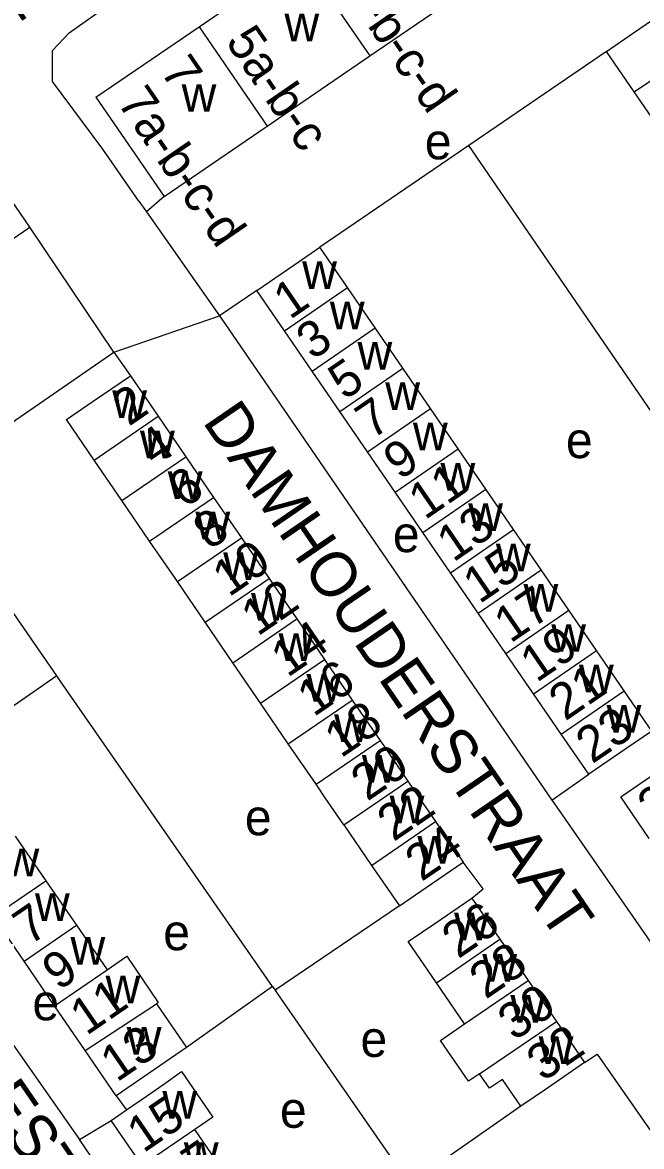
# Model space of a CAD drawing. Extents: x 157569 to 159501, y 382907 to 384670.
# Drawn here: x 158188.6 to 158257.4, y 383461.2 to 383586.2 of the extents above; entities that cross this region are included whole.
import ezdxf

# ---------------------------------------------------------------- set-up
doc = ezdxf.new("R2010")
doc.units = 0
for name, color, linetype in [('BLT_Basislijn', 7, 'Continuous'), ('BLT_Bebouwing', 7, 'Continuous'), ('BLT_Centroide', 7, 'Continuous'), ('BLT_Huisnummer', 7, 'Continuous'), ('BLT_Huisnummer_ tussenligend', 7, 'Continuous'), ('BLT_Huisnummer_reeks', 7, 'Continuous'), ('BLT_Onderverdeling_panden', 7, 'Continuous'), ('BLT_Straatnaam', 7, 'Continuous'), ('BLT_Vlakafsluiter', 7, 'Continuous')]:
    doc.layers.add(name, color=color, linetype=linetype)

msp = doc.modelspace()

# ---------------------------------------------------------------- linework, layer by layer
at = {"layer": 'BLT_Basislijn'}
for p, q in [((158253.53, 383582.97), (158238.22, 383572.51)), ((158238.22, 383572.51), (158221.67, 383561.19)), ((158263.17, 383536.11), (158238.22, 383572.51)), ((158201.56, 383566.31), (158202.39, 383565.13)), ((158204.37, 383566.82), (158202.39, 383565.13)), ((158202.39, 383565.13), (158210.52, 383553.57)), ((158198.77, 383549.53), (158189.43, 383563.44)), ((158214.66, 383556.38), (158210.52, 383553.57)), ((158177.61, 383534.96), (158198.77, 383549.53)), ((158198.77, 383549.53), (158200.61, 383546.91)), ((158192.45, 383513.55), (158177.61, 383534.96)), ((158192.45, 383513.55), (158186.37, 383509.34)), ((158247.46, 383499.74), (158251.56, 383502.6)), ((158230.51, 383487.97), (158216.7, 383478.6)), ((158216.41, 383479.02), (158206.85, 383472.24)), ((158216.41, 383479.02), (158216.7, 383478.6)), ((158199.04, 383466.86), (158200.16, 383465.29)), ((158244.02, 383465.72), (158231.59, 383457.07)), ((158194.95, 383462), (158198.47, 383464.12)), ((158208.98, 383441.63), (158194.95, 383462))]:
    msp.add_line(p, q, dxfattribs=at)
for points in [[(158201.56, 383566.31), (158197.56, 383572.1), (158191.94, 383579.6), (158191.94, 383583.05), (158193.8, 383585.03), (158215.11, 383600.13)], [(158210.52, 383553.57), (158210.7, 383553.32), (158247.46, 383499.74)], [(158216.41, 383479.02), (158192.82, 383513.01), (158192.45, 383513.55)], [(158247.46, 383499.74), (158247.67, 383499.43), (158262.36, 383478.24), (158263.44, 383478.98)], [(158169.81, 383497.81), (158170.18, 383497.34), (158194.51, 383462.64), (158194.95, 383462)], [(158238.55, 383488.85), (158239.83, 383489.88), (158237.6, 383492.84)], [(158216.7, 383478.6), (158216.97, 383478.21), (158231.59, 383457.07)], [(158251.08, 383470.55), (158252.5, 383471.5), (158264.68, 383454)]]:
    msp.add_lwpolyline(points, dxfattribs=at)
at = {"layer": 'BLT_Bebouwing'}
for p, q in [((158208.24, 383585.71), (158219.63, 383593.5)), ((158227.21, 383582.46), (158238.6, 383590.25)), ((158196.77, 383577.87), (158208.24, 383585.71)), ((158215.82, 383574.66), (158227.21, 383582.46)), ((158256.61, 383578.46), (158253.53, 383582.97)), ((158196.77, 383577.87), (158204.37, 383566.82)), ((158259.7, 383573.95), (158256.61, 383578.46)), ((158204.37, 383566.82), (158215.82, 383574.66)), ((158189.43, 383563.44), (158185.14, 383569.68)), ((158224.74, 383556.71), (158221.67, 383561.19)), ((158217.73, 383551.9), (158214.66, 383556.38)), ((158227.82, 383552.23), (158224.74, 383556.71)), ((158220.81, 383547.42), (158217.73, 383551.9)), ((158230.89, 383547.75), (158227.82, 383552.23)), ((158233.97, 383543.26), (158230.89, 383547.75)), ((158200.61, 383546.91), (158203.69, 383542.4)), ((158223.88, 383542.94), (158220.81, 383547.42)), ((158226.96, 383538.45), (158223.88, 383542.94)), ((158237.04, 383538.78), (158233.97, 383543.26)), ((158203.69, 383542.4), (158206.77, 383537.9)), ((158240.12, 383534.3), (158237.04, 383538.78)), ((158199.66, 383533.03), (158196.58, 383537.54)), ((158206.77, 383537.9), (158209.85, 383533.39)), ((158230.04, 383533.97), (158226.96, 383538.45)), ((158233.11, 383529.49), (158230.04, 383533.97)), ((158243.2, 383529.82), (158240.12, 383534.3)), ((158202.75, 383528.53), (158199.66, 383533.03)), ((158209.85, 383533.39), (158212.94, 383528.88)), ((158212.94, 383528.88), (158216.02, 383524.38)), ((158236.19, 383525.01), (158233.11, 383529.49)), ((158246.27, 383525.33), (158243.2, 383529.82)), ((158205.83, 383524.02), (158202.75, 383528.53)), ((158239.26, 383520.53), (158236.19, 383525.01)), ((158249.35, 383520.85), (158246.27, 383525.33)), ((158208.91, 383519.51), (158205.83, 383524.02)), ((158216.02, 383524.38), (158219.1, 383519.87)), ((158242.34, 383516.04), (158239.26, 383520.53)), ((158252.42, 383516.37), (158249.35, 383520.85)), ((158212, 383515.01), (158208.91, 383519.51)), ((158219.1, 383519.87), (158222.18, 383515.37)), ((158255.5, 383511.89), (158252.42, 383516.37)), ((158215.08, 383510.5), (158212, 383515.01)), ((158222.18, 383515.37), (158225.27, 383510.86)), ((158245.41, 383511.56), (158242.34, 383516.04)), ((158248.49, 383507.08), (158245.41, 383511.56)), ((158258.57, 383507.41), (158255.5, 383511.89)), ((158218.16, 383506), (158215.08, 383510.5)), ((158225.27, 383510.86), (158228.35, 383506.35)), ((158228.35, 383506.35), (158231.43, 383501.85)), ((158251.56, 383502.6), (158248.49, 383507.08)), ((158221.25, 383501.49), (158218.16, 383506)), ((158258.28, 383495.46), (158255.1, 383500.1)), ((158224.33, 383496.99), (158227.42, 383492.48)), ((158234.52, 383497.34), (158237.6, 383492.84)), ((158187.82, 383495.73), (158191.22, 383490.77)), ((158227.42, 383492.48), (158230.51, 383487.97)), ((158191.22, 383490.77), (158194.62, 383485.82)), ((158238.55, 383488.85), (158241.68, 383484.27)), ((158188.79, 383481.82), (158185.39, 383486.78)), ((158194.62, 383485.82), (158198.01, 383480.87)), ((158241.68, 383484.27), (158244.81, 383479.7)), ((158192.18, 383476.87), (158188.79, 383481.82)), ((158237.75, 383474.86), (158234.62, 383479.44)), ((158244.81, 383479.7), (158247.95, 383475.12)), ((158195.58, 383471.91), (158192.18, 383476.87)), ((158203.52, 383477.09), (158206.85, 383472.24)), ((158247.95, 383475.12), (158251.08, 383470.55)), ((158199.04, 383466.86), (158195.58, 383471.91)), ((158198.47, 383464.12), (158200.16, 383465.29)), ((158201.9, 383459.11), (158198.47, 383464.12)), ((158211.2, 383458.12), (158207.77, 383463.13))]:
    msp.add_line(p, q, dxfattribs=at)
for points in [[(158253.53, 383582.97), (158256.52, 383585.01), (158260.65, 383587.83)], [(158184.96, 383558.17), (158187.03, 383559.58), (158186, 383561.08), (158189.43, 383563.44)], [(158214.66, 383556.38), (158218.78, 383559.21), (158221.67, 383561.19)], [(158196.58, 383537.54), (158193.5, 383542.04), (158196.48, 383544.08), (158200.61, 383546.91)], [(158258.57, 383507.41), (158255.68, 383505.43), (158251.56, 383502.6)], [(158255.1, 383500.1), (158259.22, 383502.93), (158262.19, 383504.96), (158265.38, 383500.32)], [(158224.33, 383496.99), (158222.27, 383500), (158221.25, 383501.49)], [(158231.43, 383501.85), (158232.7, 383500), (158234.52, 383497.34)], [(158230.51, 383487.97), (158233.48, 383490.01), (158237.6, 383492.84)], [(158234.62, 383479.44), (158231.49, 383484.01), (158234.43, 383486.02), (158238.55, 383488.85)], [(158198.01, 383480.87), (158200.21, 383482.38), (158203.7, 383477.22), (158203.52, 383477.09)], [(158239.42, 383469.32), (158238.2, 383468.48), (158235.09, 383473.01), (158237.75, 383474.86)], [(158206.85, 383472.24), (158199.04, 383466.86)], [(158251.08, 383470.55), (158246.95, 383467.73), (158244.02, 383465.72)], [(158200.16, 383465.29), (158202.41, 383466.82), (158204.33, 383468.14), (158206.29, 383469.55), (158209.78, 383464.49), (158207.77, 383463.13)], [(158244.02, 383465.72), (158241.98, 383468.69), (158240.53, 383467.7), (158239.42, 383469.32)]]:
    msp.add_lwpolyline(points, dxfattribs=at)
at = {"layer": 'BLT_Onderverdeling_panden'}
for p, q in [((158219.63, 383593.5), (158227.21, 383582.46)), ((158208.24, 383585.71), (158215.82, 383574.66)), ((158256.61, 383578.46), (158263.73, 383583.32)), ((158217.73, 383551.9), (158224.74, 383556.71)), ((158220.81, 383547.42), (158227.82, 383552.23)), ((158223.88, 383542.94), (158230.89, 383547.75)), ((158226.96, 383538.45), (158233.97, 383543.26)), ((158196.58, 383537.54), (158203.69, 383542.4)), ((158230.04, 383533.97), (158237.04, 383538.78)), ((158199.66, 383533.03), (158206.77, 383537.9)), ((158233.11, 383529.49), (158240.12, 383534.3)), ((158202.75, 383528.53), (158209.85, 383533.39)), ((158205.83, 383524.02), (158212.94, 383528.88)), ((158236.19, 383525.01), (158243.2, 383529.82)), ((158239.26, 383520.53), (158246.27, 383525.33)), ((158208.91, 383519.51), (158216.02, 383524.38)), ((158242.34, 383516.04), (158249.35, 383520.85)), ((158212, 383515.01), (158219.1, 383519.87)), ((158245.41, 383511.56), (158252.42, 383516.37)), ((158215.08, 383510.5), (158222.18, 383515.37)), ((158248.49, 383507.08), (158255.5, 383511.89)), ((158218.16, 383506), (158225.27, 383510.86)), ((158221.25, 383501.49), (158228.35, 383506.35)), ((158224.33, 383496.99), (158231.43, 383501.85)), ((158227.42, 383492.48), (158234.52, 383497.34)), ((158185.39, 383486.78), (158191.22, 383490.77)), ((158188.79, 383481.82), (158194.62, 383485.82)), ((158234.62, 383479.44), (158241.68, 383484.27)), ((158192.18, 383476.87), (158198.01, 383480.87)), ((158237.75, 383474.86), (158244.81, 383479.7)), ((158195.58, 383471.91), (158203.52, 383477.09)), ((158239.42, 383469.32), (158247.95, 383475.12)), ((158207.77, 383463.13), (158201.9, 383459.11))]:
    msp.add_line(p, q, dxfattribs=at)
at = {"layer": 'BLT_Vlakafsluiter'}
msp.add_line((158198.77, 383549.53), (158210.52, 383553.57), dxfattribs=at)

# ---------------------------------------------------------------- texts
at = {"layer": 'BLT_Centroide'}
for s, p in [('w', (158217.73, 383584.09)), ('w', (158206.3, 383576.25)), ('e', (158233.33, 383570.97)), ('w', (158219.7, 383556.56)), ('w', (158222.77, 383552.06)), ('w', (158225.85, 383547.59)), ('w', (158198.59, 383542.22)), ('w', (158228.93, 383543.09)), ('w', (158232.01, 383538.62)), ('w', (158201.68, 383537.72)), ('e', (158249.01, 383537.75)), ('w', (158204.76, 383533.22)), ('w', (158235.07, 383534.12)), ('w', (158238.15, 383529.66)), ('w', (158207.84, 383528.72)), ('e', (158229.78, 383527.3)), ('w', (158241.23, 383525.16)), ('w', (158210.93, 383524.19)), ('w', (158244.3, 383520.69)), ('w', (158214.01, 383519.69)), ('w', (158247.38, 383516.22)), ('w', (158217.09, 383515.19)), ('w', (158220.18, 383510.69)), ('w', (158250.46, 383511.72)), ('w', (158253.53, 383507.25)), ('w', (158223.26, 383506.19)), ('w', (158226.34, 383501.66)), ('w', (158229.42, 383497.16)), ('e', (158213.33, 383495.83)), ('w', (158232.51, 383492.66)), ('w', (158186.61, 383491.25)), ('w', (158190, 383486.31)), ('w', (158236.59, 383484.16)), ('e', (158204.26, 383483.05)), ('w', (158193.95, 383481.44)), ('w', (158239.72, 383479.56)), ('w', (158197.85, 383477.16)), ('e', (158189.72, 383475.26)), ('w', (158242.84, 383475)), ('w', (158200.2, 383471.44)), ('e', (158226.18, 383471.19)), ('w', (158245.98, 383470.41)), ('w', (158204.16, 383464.34)), ('e', (158217.23, 383463.31)), ('w', (158206.55, 383458.62))]:
    msp.add_text(s, height=4, dxfattribs=at).set_placement(p)
at = {"layer": 'BLT_Huisnummer'}
for s, rotation, p in [('1', 34.4568, (158218.33, 383553.08)), ('5', 34.4568, (158224.41, 383544.13)), ('2', 34.3913, (158200.43, 383541.22)), ('9', 34.4568, (158230.55, 383535.23)), ('6', 34.3913, (158206.62, 383532.1)), ('13', 34.4568, (158236.49, 383526.11)), ('10', 34.3913, (158211.55, 383522.24)), ('17', 34.4568, (158242.84, 383517.1)), ('14', 34.3913, (158218.06, 383513.29)), ('18', 34.3913, (158224, 383504.34)), ('23', 34.4568, (158251.93, 383503.7)), ('25', 34.4568, (158258.78, 383496.81)), ('24', 34.3913, (158232.96, 383490.61)), ('26', 34.3913, (158237.04, 383482.03)), ('9', 34.4233, (158192.63, 383478.48)), ('13', 34.4233, (158199.1, 383468.31)), ('32', 34.3913, (158246.47, 383468.36)), ('15', 34.4233, (158202.05, 383460.44))]:
    msp.add_text(s, height=4, rotation=rotation, dxfattribs=at).set_placement(p)
at = {"layer": 'BLT_Huisnummer_ tussenligend'}
for s, rotation, p in [('3', 34.4568, (158220.87, 383548.58)), ('7', 34.4568, (158227.45, 383539.76)), ('4', 34.3913, (158203.33, 383536.71)), ('11', 34.4568, (158233.34, 383530.82)), ('8', 34.3913, (158209.4, 383527.47)), ('15', 34.4568, (158239.4, 383521.48)), ('12', 34.3913, (158214.74, 383517.88)), ('19', 34.4568, (158245.75, 383512.73)), ('16', 34.3913, (158220.97, 383508.92)), ('21', 34.4568, (158248.93, 383508.46)), ('20', 34.3913, (158226.93, 383499.54)), ('22', 34.3913, (158229.85, 383495.05)), ('7', 34.4233, (158189.39, 383483.51)), ('28', 34.3913, (158240.09, 383477.53)), ('11', 34.4233, (158195.72, 383473.49)), ('30', 34.3913, (158243.26, 383472.89)), ('17', 34.4233, (158205.65, 383455.49))]:
    msp.add_text(s, height=4, rotation=rotation, dxfattribs=at).set_placement(p)
at = {"layer": 'BLT_Huisnummer_reeks'}
for s, rotation, p in [('3a-b-c-d', 304.5078, (158222.51, 383592.23)), ('5a-b-c', 304.5078, (158211.1, 383584.05)), ('7', 304.4574, (158203.86, 383580.73)), ('7a-b-c-d', 304.5078, (158199.06, 383577.31))]:
    msp.add_text(s, height=4, rotation=rotation, dxfattribs=at).set_placement(p)
at = {"layer": 'BLT_Straatnaam'}
for s, height, rotation, p in [('SCHULTINGHSTRAAT', 4.9999, 34.6144, (158164.61, 383569.81)), ('DAMHOUDERSTRAAT', 5, 304.3955, (158208.54, 383541.81)), ('KRABBESTRAAT', 4.9999, 304.4805, (158171.19, 383485.14))]:
    msp.add_text(s, height=height, rotation=rotation, dxfattribs=at).set_placement(p)

doc.saveas('drawing.dxf')
